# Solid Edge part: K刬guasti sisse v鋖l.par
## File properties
Author: Türk
Template: Iso Part.par
Last saved by: Türk
Revision: 14
Application: Solid Edge
Accuracy: 0,990
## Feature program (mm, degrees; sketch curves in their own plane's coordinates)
pattern "PatternOccurrence_2"  XOffset = 12 deg
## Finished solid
Body 1: solid body, 550 faces, 1446 edges, 900 vertices.
  Faces by surface: plane 454, cylinder 96
  Edges by curve: line 1080, circle 366
Bounding box of the edges (mm): 30.000 x 445.000 x 30.000, from (-15, -85, -15) to (15, 360, 15).
Cylindrical faces by radius (mm): R14 x4, R15 x92
Planar faces by outward normal: +x 6, +y 92, +z 3, -x 6, -y 92, -z 3, oblique 252
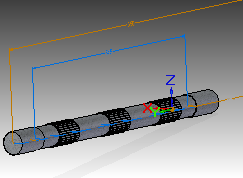
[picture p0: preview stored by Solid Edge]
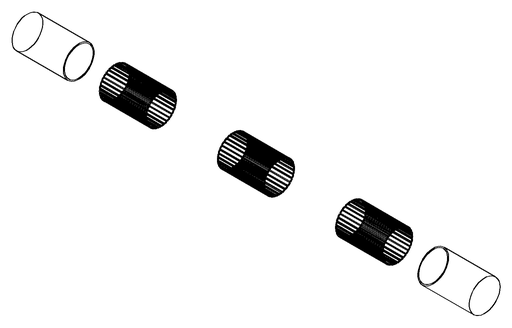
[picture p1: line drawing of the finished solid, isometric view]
